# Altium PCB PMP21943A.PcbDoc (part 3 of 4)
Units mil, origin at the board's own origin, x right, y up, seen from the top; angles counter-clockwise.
Board outline 5100 x 3900 mil, 8 copper layers (Top Layer, Signal Layer 1, Signal Layer 2, Signal Layer 3, Signal Layer 4, Signal Layer 5, Signal Layer 6, Bottom Layer), stack 61.6 mil thick; 371 components, 163 nets, 967 pads, 1147 vias.
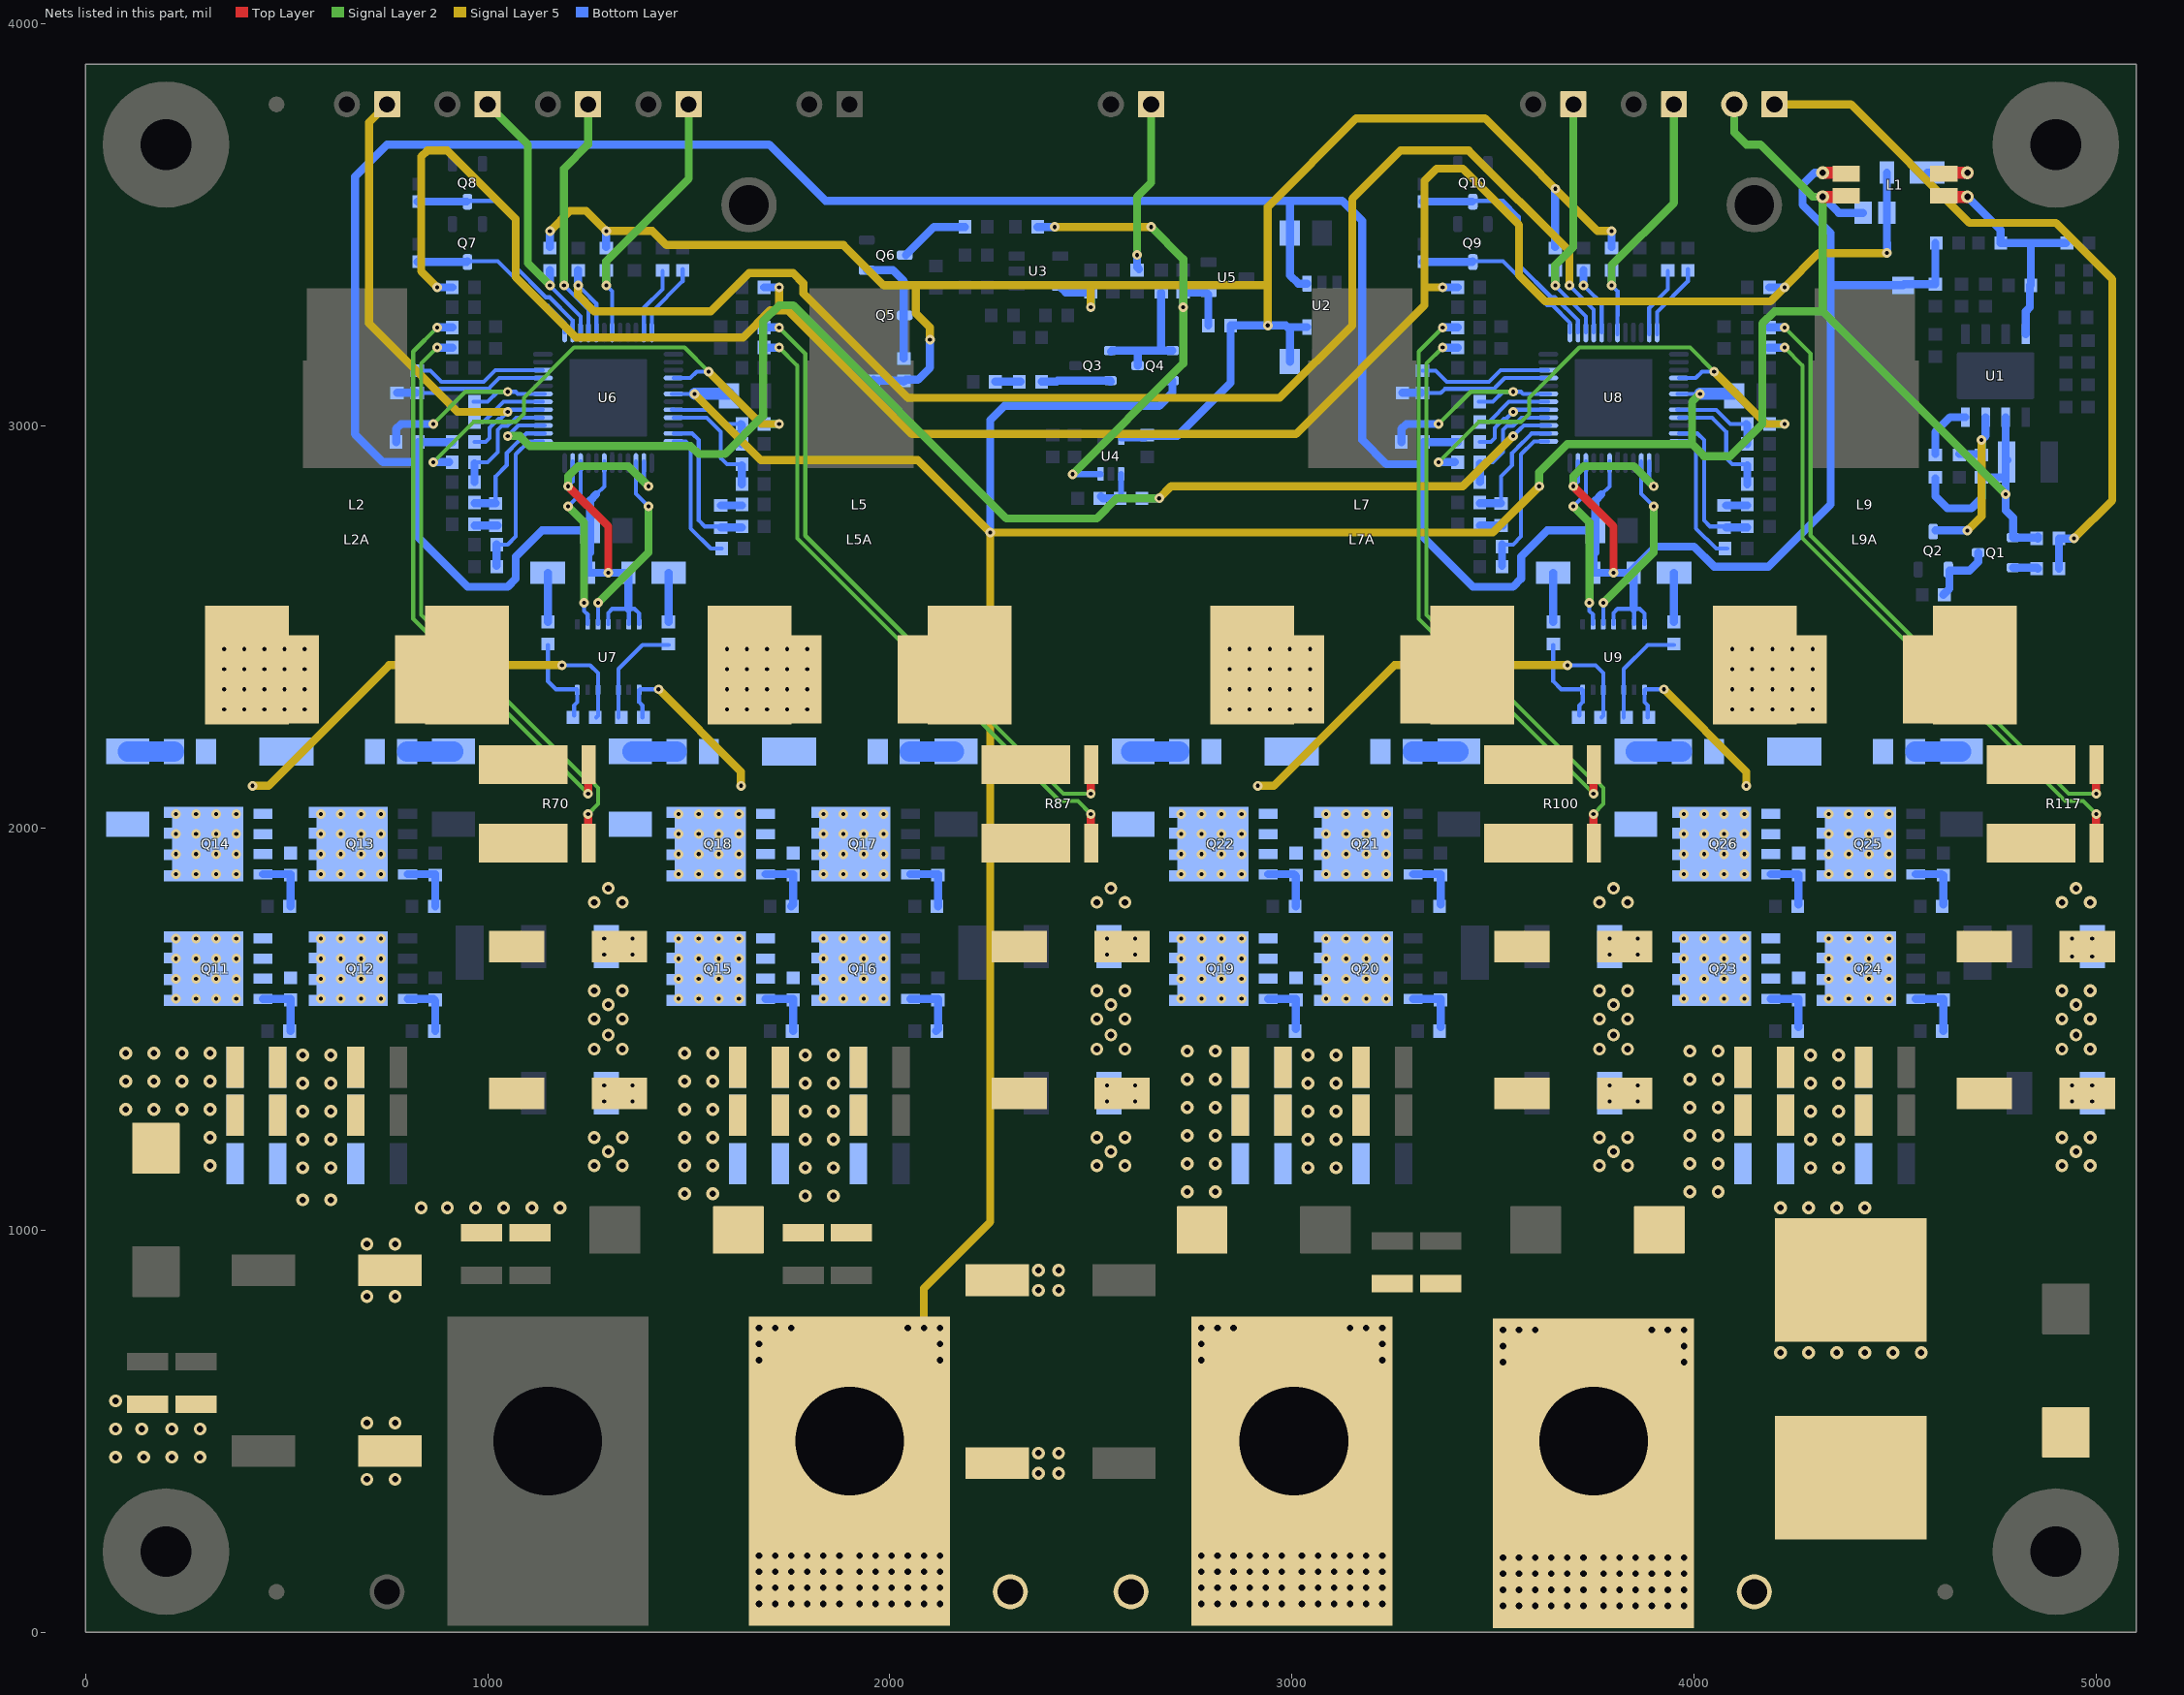
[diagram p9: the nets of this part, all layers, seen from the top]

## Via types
v1: diameter 32, hole 16, Top Layer to Bottom Layer, tented both sides, 555 vias
v2: diameter 24, hole 10, Top Layer to Bottom Layer, tented both sides, 534 vias
v3: diameter 20, hole 10, Top Layer to Bottom Layer, tented both sides, 58 vias

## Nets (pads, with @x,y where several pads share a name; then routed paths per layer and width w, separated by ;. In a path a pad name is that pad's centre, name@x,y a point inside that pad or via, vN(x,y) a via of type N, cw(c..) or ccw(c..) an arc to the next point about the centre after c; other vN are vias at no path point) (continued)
NetC20_1: C20.1 R29.2 U6.28 | length 295.6
  Bottom Layer w10: R29.2@967.56,2910 1000,2910 1025,2935 1025,2990 1035,3000 1049.72,3000 1059.85,3010.13 1060.3,3010.13 1070.96,3020.79 U6.28@1137.6,3020.79
  Bottom Layer w20: C20.1@967.56,2860 R29.2@967.56,2907.44
NetC21_2: C21.2 C22.2 U6.26 | length 305.9
  Bottom Layer w10: C22.2@1020,2805 C22.2@1020,2807.56 1020,2875 1047.56,2902.56 1047.56,2932.56 1075.13,2960.13 1075.3,2960.13 1089.87,2974.7 1089.87,2974.87 1096.42,2981.42 U6.26@1141.54,2981.42
  Bottom Layer w20: C21.2@967.44,2807.56 C22.2@1020,2807.56
NetC22_1: C22.1 R30.1 | length 57.4
  Bottom Layer w20: R30.1@967.56,2752.44 C22.1@1025,2752.44
NetC23_1: C23.1 R31.2 U6.8 | length 237
  Bottom Layer w10: U6.8@1458.46,3040.47 U6.8@1462.4,3040.47 1550,3040 1555,3040 1590,3005 R31.2@1630,3005
  Bottom Layer w20: R31.2@1630,3005 1632.44,3002.56 C23.1@1632.44,2955
NetC28_2: C28.2 R38.1 U7.13 | length 238.9
  Bottom Layer w10: R38.1@1150,2455 1150,2365 1170,2345 1221.54,2345 U7.13@1223.23,2343.31 1223.23,2313.23 1215,2305 C28.2@1215,2280
NetC30_1: C30.1 R42.1 U6.31 | length 537.3
  Signal Layer 2 w10: v2(865,3005) 945,3085 v2(1050,3085)
  Bottom Layer w10: C30.1@965,3060 C30.1@967.56,3060 1000,3060 1025,3085 v2(1050,3085) 1070,3085 1075,3080 ; 1075,3079.84 U6.31@1141.54,3079.84
  Bottom Layer w20: R42.1@772.44,2960 772.44,2992.44 785,3005 v2(865,3005)
NetC32_1: C32.1 R43.1 U7.10 | length 269.9
  Bottom Layer w10: C32.1@1325,2275 1325.59,2275.59 U7.10@1325.59,2343.31 1325.59,2395.59 1385,2455 R43.1@1450,2455
NetC33_1: C33.1 U6.12 | length 350.6
  Bottom Layer w10: U6.12@1462.4,2961.73 1493.27,2961.73 1505,2950 1505,2745 1555,2695 C33.1@1582.44,2695
NetC37_1: C37.1 C40.1 U6.11 | length 383.1
  Bottom Layer w10: U6.11@1462.4,2981.42 1508.58,2981.42 1525,2965 1525,2765 1540,2750 C37.1@1580,2750
  Bottom Layer w20: C37.1@1580,2747.44 C40.1@1632.44,2747.44
NetC37_2: C37.2 R48.2 | length 52.6
  Bottom Layer w20: C37.2@1580,2802.56 R48.2@1632.56,2802.56
NetC38_1: C38.1 R46.2 U6.9 | length 306.7
  Bottom Layer w10: U6.9@1462.4,3020.79 1545,3020.79 1580,2985.79 1580,2920 1595,2905 C38.1@1632.44,2905 C38.1@1635,2905
  Bottom Layer w20: R46.2@1632.44,2855 C38.1@1632.44,2902.56
NetC39_1: C39.1 R47.2 U6.25 | length 393.8
  Bottom Layer w10: R47.2@1022.56,2705 1050,2705 1070,2725 1070,2929.55 1102.19,2961.73 U6.25@1137.6,2961.73
  Bottom Layer w20: C39.1@1022.56,2652.44 R47.2@1022.56,2705
NetC41_1: C41.1 R49.2 U8.28 | length 295.6
  Bottom Layer w10: R49.2@3467.56,2910 3500,2910 3525,2935 3525,2990 3535,3000 3549.72,3000 3559.85,3010.13 3560.3,3010.13 3570.96,3020.79 U8.28@3637.6,3020.79
  Bottom Layer w20: C41.1@3467.56,2860 R49.2@3467.56,2907.44
NetC42_2: C42.2 C43.2 U8.26 | length 305.9
  Bottom Layer w10: C43.2@3520,2805 C43.2@3520,2807.56 3520,2875 3547.56,2902.56 3547.56,2932.56 3575.13,2960.13 3575.3,2960.13 3589.87,2974.7 3589.87,2974.87 3596.42,2981.42 U8.26@3641.54,2981.42
  Bottom Layer w20: C42.2@3467.44,2807.56 C43.2@3520,2807.56
NetC43_1: C43.1 R50.1 | length 57.4
  Bottom Layer w20: R50.1@3467.56,2752.44 C43.1@3525,2752.44
NetC44_1: C44.1 R51.2 U8.8 | length 237
  Bottom Layer w10: U8.8@3958.46,3040.47 U8.8@3962.4,3040.47 4050,3040 4055,3040 4090,3005 R51.2@4130,3005
  Bottom Layer w20: R51.2@4130,3005 4132.44,3002.56 C44.1@4132.44,2955
NetC49_2: C49.2 R58.1 U9.13 | length 238.9
  Bottom Layer w10: R58.1@3650,2455 3650,2365 3670,2345 3721.54,2345 U9.13@3723.23,2343.31 3723.23,2313.23 3715,2305 C49.2@3715,2280
NetC51_1: C51.1 R62.1 U8.31 | length 537.3
  Signal Layer 2 w10: v2(3365,3005) 3445,3085 v2(3550,3085)
  Bottom Layer w10: C51.1@3465,3060 C51.1@3467.56,3060 3500,3060 3525,3085 v2(3550,3085) 3570,3085 3575,3080 ; 3575,3079.84 U8.31@3641.54,3079.84
  Bottom Layer w20: R62.1@3272.44,2960 3272.44,2992.44 3285,3005 v2(3365,3005)
NetC53_1: C53.1 R63.1 U9.10 | length 269.9
  Bottom Layer w10: C53.1@3825,2275 3825.59,2275.59 U9.10@3825.59,2343.31 3825.59,2395.59 3885,2455 R63.1@3950,2455
NetC54_1: C54.1 U8.12 | length 350.6
  Bottom Layer w10: U8.12@3962.4,2961.73 3993.27,2961.73 4005,2950 4005,2745 4055,2695 C54.1@4082.44,2695
NetC58_1: C58.1 C61.1 U8.11 | length 383.1
  Bottom Layer w10: U8.11@3962.4,2981.42 4008.58,2981.42 4025,2965 4025,2765 4040,2750 C58.1@4080,2750
  Bottom Layer w20: C58.1@4080,2747.44 C61.1@4132.44,2747.44
NetC58_2: C58.2 R68.2 | length 52.6
  Bottom Layer w20: C58.2@4080,2802.56 R68.2@4132.56,2802.56
NetC59_1: C59.1 R66.2 U8.9 | length 306.7
  Bottom Layer w10: U8.9@3962.4,3020.79 4045,3020.79 4080,2985.79 4080,2920 4095,2905 R66.2@4132.44,2905 R66.2@4135,2905
  Bottom Layer w20: C59.1@4132.44,2855 R66.2@4132.44,2902.56
NetC60_1: C60.1 R67.2 U8.25 | length 393.8
  Bottom Layer w10: R67.2@3522.56,2705 3550,2705 3570,2725 3570,2929.55 3602.19,2961.73 U8.25@3637.6,2961.73
  Bottom Layer w20: C60.1@3522.56,2652.44 R67.2@3522.56,2705
NetC62_2: C62.2 R69.2 | length 115
  Bottom Layer w50: R69.2@105,2190 C62.2@220,2190
NetC63_2: C63.2 R75.2 | length 115
  Bottom Layer w50: C63.2@800,2190 R75.2@915,2190
NetC67_1: C67.1 C68.1 C69.1 C70.1 C71.1 L3.2 Q11.5 Q11.6 Q11.7 Q11.8 Q11.9 Q14.5 Q14.6 Q14.7 Q14.8 Q14.9 R69.1
  other v1: 310,1160 310,1230 100,1300 170,1300 240,1300 310,1300 100,1370 170,1370 240,1370 310,1370 100,1440 170,1440 240,1440 310,1440
  other v2: 225,1575 275,1575 325,1575 375,1575 225,1625 275,1625 325,1625 375,1625 225,1675 275,1675 325,1675 375,1675 225,1725 275,1725 325,1725 375,1725 225,1885 275,1885 325,1885 375,1885 225,1935 275,1935 325,1935 375,1935 225,1985 275,1985 325,1985 375,1985 225,2035 275,2035 325,2035 375,2035
NetC72_2: C72.2 R82.2
  other v2: 1290,1320 1360,1320 1290,1360 1360,1360
NetC73_2: C73.2 R83.2
  other v2: 1290,1685 1360,1685 1290,1725 1360,1725
NetC74_2: C74.2 J13.1 L4.2 T4.1 TP8.1
  other v1: 3525,65 3565,65 3605,65 3645,65 3685,65 3725,65 3775,65 3815,65 3855,65 3895,65 3935,65 3975,65 3525,105 3565,105 3605,105 3645,105 3685,105 3725,105 3775,105 3815,105 3855,105 3895,105 3935,105 3975,105 3525,145 3565,145 3605,145 3645,145 3685,145 3725,145 3775,145 3815,145 3855,145 3895,145 3935,145 3975,145 3525,185 3565,185 3605,185 3645,185 3685,185 3725,185 3775,185 3815,185 3855,185 3895,185 3935,185 3975,185 3525,671.27 3975,671.27 3525,711.27 3975,711.27 3525,751.27 3565,751.27 3605,751.27 3895,751.27 3935,751.27 3975,751.27
NetC80_2: C80.2 R84.2 | length 110
  Bottom Layer w50: R84.2@1360,2190 C80.2@1470,2190
NetC81_2: C81.2 R85.2
  other v2: 2540,1320 2610,1320 2540,1360 2610,1360
NetC82_2: C82.2 R86.2
  other v2: 2540,1685 2610,1685 2540,1725 2610,1725
NetC88_2: C88.2 R94.2 | length 110
  Bottom Layer w50: C88.2@2050,2190 R94.2@2160,2190
NetC92_1: C92.1 C93.1 C94.1 C95.1 C96.1 L6.2 Q15.5 Q15.6 Q15.7 Q15.8 Q15.9 Q18.5 Q18.6 Q18.7 Q18.8 Q18.9 R84.1
  other v1: 1490,1090 1560,1090 1490,1160 1560,1160 1490,1230 1560,1230 1490,1300 1560,1300 1490,1370 1560,1370 1490,1440 1560,1440
  other v2: 1475,1575 1525,1575 1575,1575 1625,1575 1475,1625 1525,1625 1575,1625 1625,1625 1475,1675 1525,1675 1575,1675 1625,1675 1475,1725 1525,1725 1575,1725 1625,1725 1475,1885 1525,1885 1575,1885 1625,1885 1475,1935 1525,1935 1575,1935 1625,1935 1475,1985 1525,1985 1575,1985 1625,1985 1475,2035 1525,2035 1575,2035 1625,2035
NetC97_2: C97.2 R99.2 | length 120
  Bottom Layer w50: R99.2@2600,2190 C97.2@2720,2190
NetC98_2: C98.2 R105.2 | length 115
  Bottom Layer w50: C98.2@3300,2190 R105.2@3415,2190
NetC102_1: C102.1 C103.1 C104.1 C105.1 C106.1 L8.2 Q19.5 Q19.6 Q19.7 Q19.8 Q19.9 Q22.5 Q22.6 Q22.7 Q22.8 Q22.9 R99.1
  other v1: 2740,1095 2810,1095 2740,1165 2810,1165 2740,1235 2810,1235 2740,1305 2810,1305 2740,1375 2810,1375 2740,1445 2810,1445
  other v2: 2725,1575 2775,1575 2825,1575 2875,1575 2725,1625 2775,1625 2825,1625 2875,1625 2725,1675 2775,1675 2825,1675 2875,1675 2725,1725 2775,1725 2825,1725 2875,1725 2725,1885 2775,1885 2825,1885 2875,1885 2725,1935 2775,1935 2825,1935 2875,1935 2725,1985 2775,1985 2825,1985 2875,1985 2725,2035 2775,2035 2825,2035 2875,2035
NetC107_2: C107.2 R112.2
  other v2: 3790,1320 3860,1320 3790,1360 3860,1360
NetC108_2: C108.2 R113.2
  other v2: 3790,1685 3860,1685 3790,1725 3860,1725
NetC114_2: C114.2 R114.2 | length 115
  Bottom Layer w50: R114.2@3855,2190 C114.2@3970,2190
NetC115_2: C115.2 R115.2
  other v2: 4940,1320 4990,1320 4940,1360 4990,1360
NetC116_2: C116.2 R116.2
  other v2: 4940,1680 4990,1680 4940,1725 4990,1725
NetC122_2: C122.2 R124.2 | length 115
  Bottom Layer w50: C122.2@4550,2190 R124.2@4665,2190
NetC126_1: C126.1 C127.1 C128.1 C129.1 C130.1 L10.2 Q23.5 Q23.6 Q23.7 Q23.8 Q23.9 Q26.5 Q26.6 Q26.7 Q26.8 Q26.9 R114.1
  other v1: 3990,1095 4060,1095 3990,1165 4060,1165 3990,1235 4060,1235 3990,1305 4060,1305 3990,1375 4060,1375 3990,1445 4060,1445
  other v2: 3975,1575 4025,1575 4075,1575 4125,1575 3975,1625 4025,1625 4075,1625 4125,1625 3975,1675 4025,1675 4075,1675 4125,1675 3975,1725 4025,1725 4075,1725 4125,1725 3975,1885 4025,1885 4075,1885 4125,1885 3975,1935 4025,1935 4075,1935 4125,1935 3975,1985 4025,1985 4075,1985 4125,1985 3975,2035 4025,2035 4075,2035 4125,2035
NetD1_1: D1.1 L1.2 | length 150
  Top Layer w30: L1.2@4630,3630 v1(4680,3630)
  Bottom Layer w20: D1.1@4580,3630 v1(4680,3630)
NetD4_2: D4.2 Q7.3 U6.37 | length 455.4
  Bottom Layer w10: Q7.3@950,3410 1025,3410 1135,3300 1148.71,3300 1191.73,3256.98 U6.37@1191.73,3232.4
  Bottom Layer w20: D4.2@825,3408.35 948.35,3408.35 Q7.3@950,3410
NetD5_1: D5.1 R38.2 | length 122.4
  Bottom Layer w20: R38.2@1150,2512.56 D5.1@1150,2635
NetD6_1: D6.1 R43.2 | length 122.4
  Bottom Layer w20: R43.2@1450,2512.56 D6.1@1450,2635
NetD7_2: D7.2 Q8.3 U6.38 | length 608.4
  Bottom Layer w10: Q8.3@950,3560 1025,3560 1065,3520 1065,3400 1145,3320 1153.99,3320 1211.42,3262.57 U6.38@1211.42,3232.4
  Bottom Layer w20: D7.2@825,3558.35 Q8.3@948.35,3558.35
NetD8_2: D8.2 Q9.3 U8.37 | length 455.4
  Bottom Layer w10: Q9.3@3450,3410 3525,3410 3635,3300 3648.71,3300 3691.73,3256.98 U8.37@3691.73,3232.4
  Bottom Layer w20: D8.2@3325,3408.35 3448.35,3408.35 Q9.3@3450,3410
NetD9_1: D9.1 R58.2 | length 122.4
  Bottom Layer w20: R58.2@3650,2512.56 D9.1@3650,2635
NetD10_1: D10.1 R63.2 | length 122.4
  Bottom Layer w20: R63.2@3950,2512.56 D10.1@3950,2635
NetD11_2: D11.2 Q10.3 U8.38 | length 608.4
  Bottom Layer w10: Q10.3@3450,3560 3525,3560 3565,3520 3565,3400 3645,3320 3653.99,3320 3711.42,3262.57 U8.38@3711.42,3232.4
  Bottom Layer w20: D11.2@3325,3558.35 Q10.3@3448.35,3558.35
NetJ1_1: J1.1 R1.2 R2.2 | length 1817
  Signal Layer 5 w20: J1.1@4200,3800 4390,3800 4685,3505 4900,3505 5040,3365 5040,2815 v2(4945,2720)
  Bottom Layer w20: R2.2@4907.56,2645 R1.2@4907.56,2720 v2(4945,2720)
NetJ3_1: J3.1 R14.2 | length 426.6
  Signal Layer 2 w20: v2(2615,3425) 2615,3570 2650,3605 J3.1@2650,3800
  Bottom Layer w20: v2(2615,3425) 2615,3395 R14.2@2620,3390
NetJ4_1: J4.1 U6.40 | length 622.6
  Signal Layer 2 w20: v2(1190,3350) 1190,3640 1250,3700 J4.1@1250,3800 J4.1@1250,3805
  Bottom Layer w10: v2(1190,3350) 1200.13,3339.87 1200.13,3339.7 1250.79,3289.04 U6.40@1250.79,3232.4
NetJ5_1: J5.1 R34.1 U6.39 | length 700.8
  Signal Layer 2 w20: J5.1@1000,3800 1100,3700 1100,3405 v2(1155,3350)
  Bottom Layer w10: v2(1155,3350) 1155,3348.43 1231.1,3272.33 U6.39@1231.1,3232.4
  Bottom Layer w20: v2(1155,3350) R34.1@1155,3387.44
NetJ6_1: J6.1 R40.1 U6.29 | length 1217.9
  Signal Layer 5 w20: J6.1@750,3800 705,3755 705,3255 925,3035 v2(1050,3035)
  Bottom Layer w10: R40.1@967.56,2960 995,2960 1005,2970 1005,2995 1007.13,2997.13 1007.13,2997.4 1027.6,3017.87 1032.87,3017.87 v2(1050,3035) 1055.47,3040.47 U6.29@1137.6,3040.47
NetJ7_1: J7.1 R33.1 U6.43 | length 697.5
  Signal Layer 2 w20: v2@1295,3355 1295,3410 1500,3615 J7.1@1500,3800
  Bottom Layer w10: v2(1295,3350) 1295,3349.82 1310,3334.82 1310,3275 ; v2@1300,3350 v2@1300,3352.35 ; U6.43@1309.84,3228.46 1309.84,3275
  Bottom Layer w20: v2(1295,3350) R33.1@1295,3387.44
NetJ8_1: J8.1 R54.1 U8.39 | length 655.2
  Signal Layer 2 w20: v2(3655,3350) 3655,3400 3700,3445 J8.1@3700,3800
  Bottom Layer w10: v2(3655,3350) 3655,3348.43 3731.1,3272.33 U8.39@3731.1,3232.4
  Bottom Layer w20: v2(3655,3350) R54.1@3655,3387.44
NetJ9_1: J9.1 R53.1 U8.43 | length 681.7
  Signal Layer 2 w20: v2(3795,3350) 3795,3400 3950,3555 J9.1@3950,3800
  Bottom Layer w10: v2(3795,3350) 3795,3349.82 3810,3334.82 3810,3275 ; v2@3800,3350 v2@3800,3352.35 ; U8.43@3809.84,3228.46 3809.84,3275
  Bottom Layer w20: v2(3795,3350) R53.1@3795,3387.44
NetL2_2: L2.2 L2A.2 R70.1
NetL5_2: L5.2 L5A.2 R87.1
NetL7_2: L7.2 L7A.2 R100.1
NetL9_2: L9.2 L9A.2 R117.1
NetQ1_2: Q1.2 R2.1 | length 62.8
  Bottom Layer w20: Q1.2@4793.31,2647.6 4852.4,2647.6 R2.1@4855,2645
NetQ2_3: Q2.3 R3.2 R8.1 U1.3 | length 477.4
  Signal Layer 5 w20: v2(4680,2740) 4715,2775 v2(4715,2965)
  Bottom Layer w20: Q2.3@4600,2740 v2(4680,2740) ; R8.1@4660,2930 4710,2930 4715,2925 R3.2@4715,2927.56 v2(4715,2965) 4725,2975 U1.3@4725,3021.65
NetQ3_1: Q3.1 Q4.1 Q4.3 R15.1 | length 330
  Bottom Layer w20: Q3.1@2550,3185 2552.4,3187.4 Q4.1@2703.31,3187.4 ; Q4.3@2616.69,3150 2616.69,3183.31 ; 2675,3190 R15.1@2675,3332.44
NetQ3_2: Q3.2 R11.2 | length 173.5
  Bottom Layer w20: R11.2@2377.56,3110 2415,3110 2417.6,3112.6 Q3.2@2548.31,3112.6 ; Q3.2@2548.31,3110 Q3.2@2550,3110
NetQ5_3: Q5.3 Q6.1 R13.2 | length 296.1
  Bottom Layer w20: Q6.1@1942.76,3387.6 2007.4,3387.6 2035,3360 R13.2@2035,3167.56
NetQ6_3: Q6.3 R23.1 | length 176.4
  Bottom Layer w20: Q6.3@2040,3425 2110,3495 R23.1@2187.44,3495
NetQ11_4: Q11.4 R71.2 R72.2 | length 148.8
  Bottom Layer w20: Q11.4@441.22,1575 510,1575 R72.2@510,1495
NetQ12_4: Q12.4 R73.1 R78.2 | length 145.9
  Bottom Layer w20: Q12.4@801.22,1575 865,1575 870,1570 R78.2@870,1495
NetQ13_4: Q13.4 R74.1 R79.2 | length 148.8
  Bottom Layer w20: Q13.4@801.22,1885 870,1885 R74.1@870,1882.44 R79.2@870,1805
NetQ14_4: Q14.4 R80.2 R81.2 | length 148.8
  Bottom Layer w20: Q14.4@441.22,1885 510,1885 R80.2@510,1882.44 R81.2@510,1805
NetQ15_4: Q15.4 R88.1 R89.2 | length 148.8
  Bottom Layer w20: Q15.4@1691.22,1575 1760,1575 R89.2@1760,1495
NetQ16_4: Q16.4 R92.1 R95.2 | length 150.9
  Bottom Layer w20: Q16.4@2051.22,1575 2120,1575 2120,1500 R95.2@2115,1495
NetQ17_4: Q17.4 R93.1 R96.2 | length 148.8
  Bottom Layer w20: Q17.4@2051.22,1885 2120,1885 R96.2@2120,1805
NetQ18_4: Q18.4 R97.1 R98.2 | length 150.9
  Bottom Layer w20: Q18.4@1691.22,1885 1760,1885 1760,1810 R98.2@1755,1805
NetQ19_4: Q19.4 R101.2 R102.2 | length 143.8
  Bottom Layer w20: Q19.4@2941.22,1575 3010,1575 R102.2@3010,1500
NetQ20_4: Q20.4 R103.1 R108.2 | length 138.8
  Bottom Layer w20: Q20.4@3301.22,1575 3370,1575 R108.2@3370,1505
NetQ21_4: Q21.4 R104.1 R109.2 | length 143.8
  Bottom Layer w20: Q21.4@3301.22,1885 3370,1885 R109.2@3370,1810
NetQ22_4: Q22.4 R110.2 R111.2 | length 145.9
  Bottom Layer w20: Q22.4@2941.22,1885 3005,1885 3010,1880 R111.2@3010,1805
NetQ23_4: Q23.4 R118.1 R119.2 | length 136.2
  Bottom Layer w20: Q23.4@4191.22,1575 R118.1@4260,1575 ; R119.2@4260,1505 R118.1@4260,1572.44
NetQ24_4: Q24.4 R122.1 R125.2 | length 146.2
  Bottom Layer w20: Q24.4@4551.22,1575 R122.1@4620,1575 ; R125.2@4620,1495 R122.1@4620,1572.44
NetQ25_4: Q25.4 R123.1 R126.2 | length 143.3
  Bottom Layer w20: Q25.4@4551.22,1885 4615,1885 R123.1@4620,1880 ; R126.2@4620,1810 R123.1@4620,1880 ; R123.1@4620,1882.44 R123.1@4620,1880
NetQ26_4: Q26.4 R127.1 R128.2 | length 143.8
  Bottom Layer w20: Q26.4@4191.22,1885 4260,1885 R128.2@4260,1810
NetR4_2: R4.2 U1.4 | length 145.2
  Bottom Layer w20: R4.2@4600,2930 4600,2985 4636.65,3021.65 U1.4@4675,3021.65
NetR11_1: R11.1 R12.2 | length 62.4
  Bottom Layer w20: R12.2@2262.56,3110 R11.1@2322.44,3110 R11.1@2325,3110
NetR18_1: R18.1 R24.2 U4.1 | length 110.5
  Bottom Layer w15: R24.2@2575,2820 2575.59,2820.59 U4.1@2575.59,2880.71
  Bottom Layer w20: R18.1@2525,2825 2530,2820 R24.2@2572.44,2820
NetR29_1: R29.1 R31.1 U6.4 | length 1251.7
  Signal Layer 2 w10: v2(865,2910) 965.13,3010.13 1070,3010.13 1090,3030.13 1090,3070 1215,3195 1490,3195 v2(1550,3135)
  Signal Layer 5 w20: v2(1550,3135) 1680,3005 v2(1725,3005)
  Bottom Layer w10: U6.4@1462.4,3119.21 1504.21,3119.21 1520,3135 v2(1550,3135)
  Bottom Layer w20: v2(865,2910) R29.1@905,2910 ; R31.1@1687.56,3005 v2(1725,3005)
NetR36_1: R36.1 R37.2 U6.33 | length 379.2
  Bottom Layer w9.8: R36.1@825,3082.44 870.21,3082.44 880,3092.23 1002.23,3092.23 1010,3100
  Bottom Layer w10: 1010,3100 1029.21,3119.21 U6.33@1137.6,3119.21 U6.33@1141.54,3119.21
  Bottom Layer w20: R37.2@775,3082.44 R36.1@822.44,3082.44
NetR36_2: R36.2 U6.34 | length 336
  Bottom Layer w10: R36.2@825,3137.56 857.44,3137.56 885,3110 990,3110 1018.9,3138.9 U6.34@1137.6,3138.9
NetR39_2: R39.2 U6.48 | length 193.3
  Bottom Layer w10: U6.48@1408.27,3228.46 U6.48@1408.27,3232.4 1408.27,3283.27 1485,3360 R39.2@1485,3387.44 R39.2@1485,3390
NetR41_2: R41.2 U6.47 | length 175.8
  Bottom Layer w10: U6.47@1388.58,3228.46 1388.58,3293.58 1435,3340 R41.2@1435,3385
NetR44_2: R44.2 U6.30 | length 190.7
  Bottom Layer w10: R44.2@967.56,3010 989.82,3010 1039.82,3060 1065,3060 ; 1065,3060.13 U6.30@1137.6,3060.13
NetR49_1: R49.1 R51.1 U8.4 | length 1251.7
  Signal Layer 2 w10: v2(3365,2910) 3465.13,3010.13 3570,3010.13 3590,3030.13 3590,3070 3715,3195 3990,3195 v2(4050,3135)
  Signal Layer 5 w20: v2(4050,3135) 4180,3005 v2(4225,3005)
  Bottom Layer w10: U8.4@3962.4,3119.21 4004.21,3119.21 4020,3135 v2(4050,3135)
  Bottom Layer w20: v2(3365,2910) R49.1@3405,2910 ; R51.1@4187.56,3005 v2(4225,3005)
NetR55_1: R55.1 U8.41 | length 176.4
  Bottom Layer w10: v2(3725,3350) 3735.13,3339.87 3735.13,3339.7 3770.47,3304.35 U8.41@3770.47,3232.4 ; R55.1@3730,3387.44 R55.1@3730,3390
  Bottom Layer w20: v2(3725,3350) R55.1@3725,3387.44
NetR56_1: R56.1 R57.2 U8.33 | length 379.2
  Bottom Layer w9.8: R56.1@3325,3082.44 3370.21,3082.44 3380,3092.23 3502.23,3092.23 3510,3100
  Bottom Layer w10: 3510,3100 3529.21,3119.21 U8.33@3637.6,3119.21 U8.33@3641.54,3119.21
  Bottom Layer w20: R57.2@3275,3082.44 R56.1@3322.44,3082.44
NetR56_2: R56.2 U8.34 | length 336
  Bottom Layer w10: R56.2@3325,3137.56 3357.44,3137.56 3385,3110 3490,3110 3518.9,3138.9 U8.34@3637.6,3138.9
NetR59_2: R59.2 U8.48 | length 193.3
  Bottom Layer w10: U8.48@3908.27,3228.46 U8.48@3908.27,3232.4 3908.27,3283.27 3985,3360 R59.2@3985,3387.44 R59.2@3985,3390
NetR60_1: R60.1 U8.29 | length 218.2
  Bottom Layer w10: R60.1@3467.56,2960 3495,2960 3505,2970 3505,2995 3507.13,2997.13 3507.13,2997.4 3527.6,3017.87 3532.87,3017.87 v2(3550,3035) 3555.47,3040.47 U8.29@3637.6,3040.47
NetR61_2: R61.2 U8.47 | length 175.8
  Bottom Layer w10: U8.47@3888.58,3228.46 3888.58,3293.58 3935,3340 R61.2@3935,3385
NetR64_2: R64.2 U8.30 | length 190.7
  Bottom Layer w10: R64.2@3467.56,3010 3489.82,3010 3539.82,3060 3565,3060 ; 3565,3060.13 U8.30@3637.6,3060.13
NetR70_3: R70.3 R76.2 | length 1472.5
  Top Layer w20: v2(1250,2085) R70.3@1250,2155
  Signal Layer 2 w10: v2(875,3245) 815,3185 815,2520 v2(1250,2085)
  Bottom Layer w20: v2(875,3245) R76.2@912.44,3245
NetR70_4: R70.4 R77.2 | length 1477.4
  Top Layer w20: R70.4@1250,1970 v2(1250,2035)
  Signal Layer 2 w10: v2(875,3195) 835.07,3155.07 835.07,2529.93 1250,2115 1260,2115 ; v2(1250,2035) 1275,2060 1275,2100.07 1260.03,2115.03
  Bottom Layer w20: v2(875,3195) R77.2@912.44,3195
NetR87_3: R87.3 R90.2 | length 1630.8
  Top Layer w20: v2(2500,2085) R87.3@2500,2155
  Signal Layer 2 w10: v2(1725,3245) 1790,3180 1790,2727.01 2432.01,2085 v2(2500,2085)
  Bottom Layer w20: R90.2@1685,3245 R90.2@1687.56,3245 v2(1725,3245)
NetR87_4: R87.4 R91.2 | length 1617.4
  Top Layer w20: R87.4@2500,1965 v2(2500,2035)
  Signal Layer 2 w10: v2(1725,3195) 1770,3150 1770,2720 2422.87,2067.13 2467.87,2067.13 v2(2500,2035)
  Bottom Layer w20: R91.2@1685,3195 R91.2@1687.56,3195 v2(1725,3195)
NetR100_3: R100.3 R106.2 | length 1472.5
  Top Layer w20: v2(3750,2085) R100.3@3750,2155
  Signal Layer 2 w10: v2(3375,3245) 3315,3185 3315,2520 v2(3750,2085)
  Bottom Layer w20: v2(3375,3245) R106.2@3412.44,3245
NetR100_4: R100.4 R107.2 | length 1487.4
  Top Layer w20: R100.4@3750,1960 v2(3750,2035)
  Signal Layer 2 w10: v2(3375,3195) 3335.07,3155.07 3335.07,2529.93 3750,2115 3760,2115 ; v2(3750,2035) 3775,2060 3775,2100.07 3760.03,2115.03
  Bottom Layer w20: v2(3375,3195) R107.2@3412.44,3195
NetR117_3: R117.3 R120.2 | length 1630.8
  Top Layer w20: v2(5000,2085) R117.3@5000,2155
  Signal Layer 2 w10: v2(4225,3245) 4290,3180 4290,2727.01 4932.01,2085 v2(5000,2085)
  Bottom Layer w20: R120.2@4185,3245 R120.2@4187.56,3245 v2(4225,3245)
NetR117_4: R117.4 R121.2 | length 1617.4
  Top Layer w20: R117.4@5000,1965 v2(5000,2035)
  Signal Layer 2 w10: v2(4225,3195) 4270,3150 4270,2720 4922.87,2067.13 4967.87,2067.13 v2(5000,2035)
  Bottom Layer w20: R121.2@4185,3195 R121.2@4187.56,3195 v2(4225,3195)
NetU6_15: U6.15 U7.3 | length 469.7
  Signal Layer 2 w20: v2(1275,2560) 1400,2685 v2(1400,2800)
  Bottom Layer w10: U7.3@1274.41,2506.69 1274.41,2559.41 v2(1275,2560) ; U6.15@1368.9,2911.54 1368.9,2831.1 v2(1400,2800)
NetU6_22: U6.22 U7.2 | length 437.9
  Signal Layer 2 w20: v2(1200,2800) 1240,2760 v2(1240,2560)
  Bottom Layer w10: v2(1200,2800) 1231.1,2831.1 U6.22@1231.1,2911.54 ; v2(1240,2560) 1240,2540 1248.82,2531.18 U7.2@1248.82,2506.69
NetU8_15: U8.15 U9.3 | length 469.7
  Signal Layer 2 w20: v2(3775,2560) 3900,2685 v2(3900,2800)
  Bottom Layer w10: U9.3@3774.41,2506.69 3774.41,2559.41 v2(3775,2560) ; U8.15@3868.9,2911.54 3868.9,2831.1 v2(3900,2800)
NetU8_22: U8.22 U9.2 | length 437.9
  Signal Layer 2 w20: v2(3700,2800) 3740,2760 v2(3740,2560)
  Bottom Layer w10: v2(3700,2800) 3731.1,2831.1 U8.22@3731.1,2911.54 ; v2(3740,2560) 3740,2540 3748.82,2531.18 U9.2@3748.82,2506.69
NFAULT: R24.1 U6.27 U8.27 | length 3358.7
  Signal Layer 2 w20: v2(1050,2975) 1080,2975 1105,2950 1505,2950 1525,2930 1590,2930 1685,3025 1685,3260 1725,3300 1760,3300 2290,2770 2515,2770 2565,2820 v2(2670,2820)
  Signal Layer 5 w20: v2(2670,2820) 2700,2850 3425,2850 v2(3550,2975)
  Bottom Layer w10: v2(1050,2975) 1067.25,2992.25 1067.71,2992.25 1076.56,3001.1 U6.27@1141.54,3001.1 ; v2(3550,2975) 3567.25,2992.25 3567.71,2992.25 3576.56,3001.1 U8.27@3641.54,3001.1
  Bottom Layer w20: R24.1@2630,2820 v2(2670,2820)
PGND: C1.2 C9.1 C24.1 C45.1 C64.2 C65.2 C66.2 C67.2 C68.2 C69.2 C70.2 C71.2 C72.1 C73.1 C74.1 C75.1 C76.1 C77.1 C78.1 C79.1 C81.1 C82.1 C83.1 C84.1 C85.1 C86.1 C87.1 C89.2 C90.2 C91.2 C92.2 C93.2 C94.2 C95.2 C96.2 C99.2 C100.2 C101.2 C102.2 C103.2 C104.2 C105.2 C106.2 C107.1 C108.1 C109.1 C110.1 C111.1 C112.1 C113.1 C115.1 C116.1 C117.1 C118.1 C119.1 C120.1 C121.1 C123.2 C124.2 C125.2 C126.2 C127.2 C128.2 C129.2 C130.2 J1.2 J10.1 J12.1 L1.4 Q1.1 Q4.2 R1.1 R3.1 R4.1 R70.2 R87.2 R100.2 R117.2 T1.1 T3.1 TP5.1 TP7.1 U1.2 U6.6 U8.6 | length 8754.7
  Top Layer w30: v1(4320,3570) L1.4@4380,3570
  Signal Layer 2 w20: v2(3615,2850) 3615,2885 3685,2955 3995,2955 ; v2(4015,3080) 3995,3060 3995,2955 ; J1.2@4100,3800 4100,3730 4130,3700 4165,3700 4295,3570 v1(4320,3570) 4320,3285 ; v2(4775,2830) 4320,3285 ; 3995,2955 4025,2925 4090,2925 4170,3005 4170,3255 4200,3285 4320,3285
  Signal Layer 5 w20: v2(1515,3080) 1680,2915 2070,2915 v2(2250,2735) ; v1(2085,756.27) 2085,855 2250,1020 v2(2250,2735) ; v2(3615,2850) 3500,2735 v2(2250,2735)
  Bottom Layer w10: U6.6@1458.62,3080 v2(1515,3080) ; U8.6@3958.62,3080 v2(4015,3080)
  Bottom Layer w20: v2(2250,2735) 2250,3015 2285,3050 2670,3050 2703.31,3083.31 Q4.2@2703.31,3112.6 ; v1(4320,3570) 4360,3530 C1.2@4420,3530 ; R4.1@4600,2870 4600,2825 4630,2795 4690,2795 4715,2820 R3.1@4715,2872.44 C9.1@4775,2872.44 ; C9.1@4775,2915 C9.1@4775,2872.44 ; U1.2@4775,3021.65 4775,2920 C9.1@4780,2915 ; R1.1@4855,2720 4855,2725 4852.4,2722.4 Q1.1@4793.31,2722.4 4793.31,2771.69 4775,2790 v2(4775,2830) C9.1@4775,2872.44
  Bottom Layer w30: v2(1515,3080) C24.1@1600,3080 ; v2(4015,3080) C45.1@4100,3080
  other v1: 1675,70 1715,70 1755,70 1795,70 1835,70 1875,70 1925,70 1965,70 2005,70 2045,70 2085,70 2125,70 2775,70 2815,70 2855,70 2895,70 2935,70 2975,70 3025,70 3065,70 3105,70 3145,70 3185,70 3225,70 1675,110 1715,110 1755,110 1795,110 1835,110 1875,110 1925,110 1965,110 2005,110 2045,110 2085,110 2125,110 2775,110 2815,110 2855,110 2895,110 2935,110 2975,110 3025,110 3065,110 3105,110 3145,110 3185,110 3225,110 1675,150 1715,150 1755,150 1795,150 1835,150 1875,150 1925,150 1965,150 2005,150 2045,150 2085,150 2125,150 2775,150 2815,150 2855,150 2895,150 2935,150 2975,150 3025,150 3065,150 3105,150 3145,150 3185,150 3225,150 1675,190 1715,190 1755,190 1795,190 1835,190 1875,190 1925,190 1965,190 2005,190 2045,190 2085,190 2125,190 2775,190 2815,190 2855,190 2895,190 2935,190 2975,190 3025,190 3065,190 3105,190 3145,190 3185,190 3225,190 700,380 770,380 2370,395 2420,395 75,435 145,435 215,435 285,435 2370,445 2420,445 75,505 140,505 215,505 285,505 700,520 770,520 75,575 1675,676.27 2125,676.27 2775,676.27 3225,676.27 4215,695 4285,695 4355,695 4425,695 4495,695 4565,695 1675,716.27 2125,716.27 2775,716.27 3225,716.27 1675,756.27 1715,756.27 1755,756.27 2045,756.27 2125,756.27 2775,756.27 2815,756.27 2855,756.27 3145,756.27 3185,756.27 3225,756.27 700,835 770,835 2370,850 2420,850 2370,900 2420,900 700,965 770,965 835,1055 900,1055 970,1055 1040,1055 1110,1055 1180,1055 4215,1055 4285,1055 4355,1055 4425,1055 540,1075 610,1075 1790,1085 1860,1085 540,1155 610,1155 1790,1155 1860,1155 3040,1155 3110,1155 4290,1155 4360,1155 1265,1160 1335,1160 2515,1160 2585,1160 3765,1160 3835,1160 4915,1160 4985,1160 1300,1195 2550,1195 3800,1195 4950,1195 540,1225 610,1225 1790,1225 1860,1225 3040,1225 3110,1225 4290,1225 4360,1225 1265,1230 1335,1230 2515,1230 2585,1230 3765,1230 3835,1230 4915,1230 4985,1230 540,1295 610,1295 1790,1295 1860,1295 3040,1295 3110,1295 4290,1295 4360,1295 540,1365 610,1365 1790,1365 1860,1365 3040,1365 3110,1365 4290,1365 4360,1365 540,1435 610,1435 1790,1435 1860,1435 3040,1435 3110,1435 4290,1435 4360,1435 1265,1450 1335,1450 2515,1450 2585,1450 3765,1450 3835,1450 4915,1450 4985,1450 1300,1485 2550,1485 3800,1485 4950,1485 1265,1525 1335,1525 2515,1525 2585,1525 3765,1525 3835,1525 4915,1525 4985,1525 1300,1560 2550,1560 3800,1560 4950,1560 1265,1595 1335,1595 2515,1595 2585,1595 3765,1595 3835,1595 4915,1595 4985,1595 1265,1815 1335,1815 2515,1815 2585,1815 3765,1815 3835,1815 4915,1815 4985,1815 1300,1850 2550,1850 3800,1850 4950,1850
REF: C13.1 R19.2 R21.1 U4.3 U5.1 | length 1286.9
  Signal Layer 2 w20: v2(2455,2880) 2730,3155 v2(2730,3295) 2730,3415 v2(2650,3495)
  Signal Layer 5 w20: v2(2410,3495) v2(2650,3495)
  Bottom Layer w15: v2(2455,2880) U4.3@2525,2880
  Bottom Layer w20: R21.1@2367.56,3495 v2(2410,3495) ; v2(2730,3295) C13.1@2730,3332.44 U5.1@2787.44,3332.44 ; R19.2@2792.44,3250 U5.1@2792.44,3327.56
SD: Q1.3 Q2.1 R7.2 | length 170.2
  Bottom Layer w20: R7.2@4620,2580 4635,2595 4635,2640 4685,2640 4706.69,2661.69 Q1.3@4706.69,2685
SW1_1: C28.1 C62.1 C63.1 L2.1 L2A.1 Q11.1 Q11.2 Q11.3 Q12.5 Q12.6 Q12.7 Q12.8 Q12.9 Q13.5 Q13.6 Q13.7 Q13.8 Q13.9 Q14.1 Q14.2 Q14.3 R71.1 R80.1 TP3.1 U7.11 | length 1104.1
  Signal Layer 5 w20: v2(415,2105) 455,2105 755,2405 v2(1185,2405)
  Bottom Layer w10: v2(1185,2405) 1255,2405 1274.41,2385.59 U7.11@1274.41,2343.31 1274.41,2279.41 C28.1@1270,2275
  other v2: 585,1575 635,1575 685,1575 735,1575 585,1625 635,1625 685,1625 735,1625 585,1675 635,1675 685,1675 735,1675 585,1725 635,1725 685,1725 735,1725 585,1885 635,1885 685,1885 735,1885 585,1935 635,1935 685,1935 735,1935 585,1985 635,1985 685,1985 735,1985 585,2035 635,2035 685,2035 735,2035 345,2295 395,2295 445,2295 495,2295 545,2295 345,2345 395,2345 445,2345 495,2345 545,2345 345,2395 395,2395 445,2395 495,2395 545,2395 345,2445 395,2445 445,2445 495,2445 545,2445
SW1_2: C49.1 C97.1 C98.1 L7.1 L7A.1 Q19.1 Q19.2 Q19.3 Q20.5 Q20.6 Q20.7 Q20.8 Q20.9 Q21.5 Q21.6 Q21.7 Q21.8 Q21.9 Q22.1 Q22.2 Q22.3 R101.1 R110.1 TP11.1 U9.11 | length 1104.1
  Signal Layer 5 w20: v2(2915,2105) 2955,2105 3255,2405 v2(3685,2405)
  Bottom Layer w10: v2(3685,2405) 3755,2405 3774.41,2385.59 U9.11@3774.41,2343.31 3774.41,2279.41 C49.1@3770,2275
  other v2: 3085,1575 3135,1575 3185,1575 3235,1575 3085,1625 3135,1625 3185,1625 3235,1625 3085,1675 3135,1675 3185,1675 3235,1675 3085,1725 3135,1725 3185,1725 3235,1725 3085,1885 3135,1885 3185,1885 3235,1885 3085,1935 3135,1935 3185,1935 3235,1935 3085,1985 3135,1985 3185,1985 3235,1985 3085,2035 3135,2035 3185,2035 3235,2035 2845,2295 2895,2295 2945,2295 2995,2295 3045,2295 2845,2345 2895,2345 2945,2345 2995,2345 3045,2345 2845,2395 2895,2395 2945,2395 2995,2395 3045,2395 2845,2445 2895,2445 2945,2445 2995,2445 3045,2445
SW2_1: C32.2 C80.1 C88.1 L5.1 L5A.1 Q15.1 Q15.2 Q15.3 Q16.5 Q16.6 Q16.7 Q16.8 Q16.9 Q17.5 Q17.6 Q17.7 Q17.8 Q17.9 Q18.1 Q18.2 Q18.3 R88.2 R97.2 TP9.1 U7.8 | length 441.6
  Signal Layer 5 w20: v2(1425,2345) 1630,2140 v2(1630,2105)
  Bottom Layer w10: U7.8@1376.77,2343.31 1376.77,2313.23 1385,2305 C32.2@1385,2275 ; U7.8@1380,2345 v2(1425,2345)
  other v2: 1835,1575 1885,1575 1935,1575 1985,1575 1835,1625 1885,1625 1935,1625 1985,1625 1835,1675 1885,1675 1935,1675 1985,1675 1835,1725 1885,1725 1935,1725 1985,1725 1835,1885 1885,1885 1935,1885 1985,1885 1835,1935 1885,1935 1935,1935 1985,1935 1835,1985 1885,1985 1935,1985 1985,1985 1835,2035 1885,2035 1935,2035 1985,2035 1595,2295 1645,2295 1695,2295 1745,2295 1795,2295 1595,2345 1645,2345 1695,2345 1745,2345 1795,2345 1595,2395 1645,2395 1695,2395 1745,2395 1795,2395 1595,2445 1645,2445 1695,2445 1745,2445 1795,2445
SW2_2: C53.2 C114.1 C122.1 L9.1 L9A.1 Q23.1 Q23.2 Q23.3 Q24.5 Q24.6 Q24.7 Q24.8 Q24.9 Q25.5 Q25.6 Q25.7 Q25.8 Q25.9 Q26.1 Q26.2 Q26.3 R118.2 R127.2 TP13.1 U9.8 | length 441.6
  Signal Layer 5 w20: v2(3925,2345) 4130,2140 v2(4130,2105)
  Bottom Layer w10: U9.8@3876.77,2343.31 3876.77,2313.23 3885,2305 C53.2@3885,2275 ; U9.8@3880,2345 v2(3925,2345)
  other v2: 4335,1575 4385,1575 4435,1575 4485,1575 4335,1625 4385,1625 4435,1625 4485,1625 4335,1675 4385,1675 4435,1675 4485,1675 4335,1725 4385,1725 4435,1725 4485,1725 4335,1885 4385,1885 4435,1885 4485,1885 4335,1935 4385,1935 4435,1935 4485,1935 4335,1985 4385,1985 4435,1985 4485,1985 4335,2035 4385,2035 4435,2035 4485,2035 4095,2295 4145,2295 4195,2295 4245,2295 4295,2295 4095,2345 4145,2345 4195,2345 4245,2345 4295,2345 4095,2395 4145,2395 4195,2395 4245,2395 4295,2395 4095,2445 4145,2445 4195,2445 4245,2445 4295,2445
SWBIAS: C2.2 C17.1 L1.1 R5.2 U1.8 | length 606
  Top Layer w30: L1.1@4620,3570 v1(4680,3570)
  Bottom Layer w20: v1(4680,3570) 4762.56,3487.44 R5.2@4762.56,3455 4840,3455 ; U1.8@4825,3228.35 4825,3285 4835,3295 4835,3350 C2.2@4837.56,3350 4837.56,3452.56 4840,3455 ; C17.1@4925,3455 4840,3455
SYNC: R35.1 U6.41 U8.40 | length 3636
  Signal Layer 5 w20: v2(1225,3350) 1225,3325 1265,3285 1555,3285 1650,3380 1760,3380 1785,3355 1785,3330 2045,3070 2970,3070 3150,3250 3150,3565 3270,3685 3440,3685 3690,3435 v2(3690,3350)
  Bottom Layer w10: v2(1225,3350) 1235.13,3339.87 1235.13,3339.7 1270.47,3304.35 U6.41@1270.47,3232.4 ; R35.1@1230,3387.44 R35.1@1230,3390 ; v2(3690,3350) 3700.13,3339.87 3700.13,3339.7 3750.79,3289.04 U8.40@3750.79,3232.4
  Bottom Layer w20: v2(1225,3350) R35.1@1225,3387.44
V5: C6.1 C12.1 C16.2 R10.2 R13.1 R19.1 R33.2 R34.2 R53.2 R54.2 U2.5 U3.5 U4.5 | length 4803.9
  Signal Layer 5 w20: v2(1155,3485) 1205,3535 1245,3535 v2(1295,3485) 1410,3485 1445,3450 1885,3450 1985,3350 2065,3350 ; v2(2100,3215) 2100,3245 2065,3280 2065,3350 ; v2(2500,3295) 2500,3350 ; v2(2940,3250) 2940,3350 ; v2(3795,3485) 3760,3485 3480,3765 3160,3765 2940,3545 2940,3350 ; 2065,3350 2500,3350 ; 2500,3350 2940,3350
  Bottom Layer w15: U4.5@2575.59,2969.29 2634.29,2969.29 C16.2@2640,2975
  Bottom Layer w20: R34.2@1155,3445 v2(1155,3485) ; R33.2@1295,3445 v2(1295,3485) ; R10.2@1960,3115 1962.56,3112.44 R13.1@2035,3112.44 ; R13.1@2035,3110 2040,3115 2070,3115 2100,3145 v2(2100,3215) ; U3.5@2425,3345 2437.56,3332.44 C12.1@2500,3332.44 v2(2500,3295) ; C16.2@2640,2975 2715,2975 2847.56,3107.56 R19.1@2847.56,3250 v2(2940,3250) 2985,3250 2989.13,3245.87 ; C6.1@2995,3160 2995,3240 2989.13,3245.87 ; U2.5@3037.6,3245.87 2989.13,3245.87 ; R54.2@3655,3445 v2(3655,3590) ; R53.2@3795,3445 v2(3795,3485)
V10: C3.1 C4.2 C8.1 C29.1 C50.1 D5.2 D6.2 D9.2 D10.2 L1.3 R6.2 R40.2 R42.2 R60.2 R62.2 U2.1 U6.14 U6.19 U6.23 U7.4 U7.6 U7.7 U8.14 U8.19 U8.23 U9.4 U9.6 U9.7 | length 10700.9
  Top Layer w20: v2(1200,2850) 1300,2750 v2@1300,2640 ; v2(3700,2850) 3800,2750 v2@3800,2640
  Top Layer w30: v1(4320,3630) L1.3@4380,3630
  Signal Layer 2 w20: v2(1200,2850) 1200,2875 1225,2900 1350,2900 v2(1400,2850) ; v2(3700,2850) 3700,2875 3725,2900 3850,2900 v2(3900,2850)
  Bottom Layer w10: v2(1200,2850) 1211.42,2861.42 U6.23@1211.42,2911.54 ; 1270,2830 1290.16,2849.32 U6.19@1290.16,2911.54 ; U7.4@1300,2506.69 1300,2535 1310,2545 1351.18,2545 ; U7.6@1351.18,2506.69 1351.18,2545 ; U7.7@1376.77,2506.69 1376.77,2533.23 1365,2545 1351.18,2545 ; U6.14@1388.58,2911.54 1388.58,2861.42 v2(1400,2850) ; v2(3700,2850) 3711.42,2861.42 U8.23@3711.42,2911.54 ; 3770,2830 3790.16,2849.32 U8.19@3790.16,2911.54 ; U9.4@3800,2506.69 3800,2535 3810,2545 3851.18,2545 ; U9.6@3851.18,2506.69 3851.18,2545 ; U9.7@3876.77,2506.69 3876.77,2533.23 3865,2545 3851.18,2545 ; U8.14@3888.58,2911.54 3888.58,2861.42 v2(3900,2850)
  Bottom Layer w20: R42.2@827.56,2960 827.56,2910 ; R42.2@830,2960 R40.2@912.44,2960 ; D5.2@1250.2,2635 D5.2@1250.2,2639.8 ; 1270,2830 1255,2815 C29.1@1255,2740 ; 1349.8,2545.2 D6.2@1349.8,2635 v2(1300,2635) 1255,2635 D5.2@1250.2,2639.8 ; U2.1@3037.6,3354.13 3015.87,3354.13 2995,3375 C3.1@2995,3480 2995,3560 ; R60.2@3412.44,2960 R62.2@3327.56,2960 3327.56,2905 ; D9.2@3750.2,2635 D9.2@3750.2,2639.8 ; 3770,2830 3755,2815 C50.1@3755,2740 ; D10.2@3845,2640 3905,2700 4000,2700 4050,2650 4185,2650 4340,2805 4340,3350 ; 3849.8,2545.2 D10.2@3849.8,2635 v2(3800,2635) 3755,2635 D9.2@3750.2,2639.8 ; v1(4320,3630) 4300,3630 4270,3600 4270,3550 4340,3480 4340,3350 ; R6.2@4600,3352.56 4522.56,3352.56 4520,3350 4340,3350 ; R6.2@4600,3355 C4.2@4600,3455 ; 827.56,2910 740,2910 670,2980 670,3620 750,3700 1700,3700 1840,3560 2995,3560 ; 827.56,2910 827.56,2722.44 950,2600 1050,2600 1070,2620 1070,2675 1135,2740 C29.1@1255,2740 ; D5.2@1250.2,2639.8 1250.2,2680.2 1255,2685 C29.1@1255,2740 ; 2995,3560 3125,3560 3175,3510 3175,2965 3235,2905 3327.56,2905 ; 3327.56,2905 3327.56,2722.44 3450,2600 3550,2600 3570,2620 3570,2675 3635,2740 C50.1@3755,2740 ; D9.2@3750.2,2639.8 3750.2,2680.2 3755,2685 C50.1@3755,2740
Vneg10: C1.1 D1.2 R32.2 R45.1 R52.2 R65.1 | length 5595
  Signal Layer 5 w20: v2(875,3345) 835,3385 835,3670 850,3685 900,3685 1070,3515 1070,3370 1220,3220 1635,3220 1702.5,3287.5 1747.5,3287.5 2055,2980 3010,2980 3330,3300 3330,3345 ; v2(1725,3345) 1725,3290 1730,3290 ; v2(3375,3345) 3330,3345 ; v2(4480,3430) 4310,3430 v2(4225,3345) 4190,3310 3630,3310 3565,3375 3565,3500 3425,3640 3360,3640 3330,3610 3330,3345
  Bottom Layer w20: v2(875,3345) R32.2@912.44,3345 ; R45.1@1687.56,3345 v2(1725,3345) ; v2(3375,3345) R52.2@3412.44,3345 ; R65.1@4187.56,3345 v2(4225,3345) ; C1.1@4479.53,3530 4479.53,3455.47 4480,3455 v2(4480,3430) ; C1.1@4479.8,3530.2 D1.2@4479.8,3630
pads on no net: FID1.1 FID2.1 FID3.1 H1.1 H2.1 H3.1 H4.1 H5.0 H6.0 H7.0 H8.0 L2.3 L2A.3 L5.3 L5A.3 L7.3 L7A.3 L9.3 L9A.3 LBL1.0 U1.9@4750,3125 U2.3 U2.4 U5.3 U6.3 U6.5 U6.7 U6.16 U6.21 U6.32 U8.3 U8.5 U8.7 U8.16 U8.21 U8.32

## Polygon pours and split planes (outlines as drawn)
+VOUT on Bottom Layer "+VOUT_L08_P1034" (solid, remove dead copper, pour order 1034): 0,0 0,1100 5100,1100 5100,0
AGND on Bottom Layer "AGND_L08_P1032" (solid, remove dead copper, pour order 1032): 4320,3900 4320,2625 0,2625 0,3900
-VIN on Bottom Layer "-VIN_L08_P1036" (solid, remove dead copper, pour order 1036): 5100,2600 5100,3900 4350,3900 4350,2600 0,2600 0,1135 5100,1135
-VIN on Signal Layer 1 "-VIN_L02_P932" (solid, remove dead copper, pour order 932): 3580,2600 3580,2835 3665,2920 3945,2920 4020,2845 4020,2600 5100,2600 5100,0 0,0 0,2600 1080,2600 1080,2850 1150,2920 1450,2920 1520,2850 1520,2600
AGND on Signal Layer 1 "AGND_L02_P930" (solid, remove dead copper, pour order 930): 0,2630 0,3900 5100,3900 5100,2630
+VOUT on Signal Layer 2 "+VOUT_L03_P951" (solid, remove dead copper, pour order 951): 0,0 0,1100 5100,1100 5100,0
AGND on Signal Layer 2 "AGND_L03_P949" (solid, remove dead copper, pour order 949): 0,2950 0,3900 5100,3900 5100,2950
-VIN on Signal Layer 2 "-VIN_L03_P952" (solid, remove dead copper, pour order 952): 0,1135 0,2925 5100,2925 5100,1135
AGND on Top Layer "AGND_L01_P910" (solid, remove dead copper, pour order 910): 0,2950 0,3900 5100,3900 5100,2950
-VIN on Top Layer "-VIN_L01_P913" (solid, remove dead copper, pour order 913): 5100,2925 5100,0 0,0 0,2925
-VIN on Signal Layer 3 "-VIN_L04_P967" (solid, remove dead copper, pour order 967): 5100,1910 5100,2925 0,2925 0,1910
AGND on Signal Layer 3 "AGND_L04_P965" (solid, remove dead copper, pour order 965): 5100,2950 5100,3900 0,3900 0,2950
PGND on Signal Layer 3 "PGND_L04_P968" (solid, remove dead copper, pour order 968): 5100,1875 5100,0 0,0 0,1875
-VIN on Signal Layer 6 "-VIN_L07_P1021" (solid, remove dead copper, pour order 1021): 3580,2600 3580,2835 3665,2920 3945,2920 4020,2845 4020,2600 5100,2600 5100,0 0,0 0,2600 1080,2600 1080,2850 1150,2920 1450,2920 1520,2850 1520,2600
AGND on Signal Layer 6 "AGND_L07_P1022" (solid, remove dead copper, pour order 1022): 5100,3900 5100,2630 0,2630 0,3900
PGND on Signal Layer 5 "PGND_L06_P987" (solid, remove dead copper, pour order 987): 0,0 0,1465 5100,1465 5100,0
AGND on Signal Layer 5 "AGND_L06_P985" (solid, remove dead copper, pour order 985): 0,2950 0,3900 5100,3900 5100,2950
-VIN on Signal Layer 5 "-VIN_L06_P988" (solid, remove dead copper, pour order 988): 5100,1500 0,1500 0,2925 5100,2925
AGND on Signal Layer 4 "AGND_L05_P1001" (solid, remove dead copper, pour order 1001): 0,2950 0,3900 5100,3900 5100,2950
+VOUT on Signal Layer 4 "+VOUT_L05_P1004" (solid, remove dead copper, pour order 1004): 5100,0 0,0 0,2915 5100,2915

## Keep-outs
Keep-Out Layer:
  lines w10: -5,-5 -5,3905 5105,3905 5105,-5 -5,-5
  text ".Layer_Name" at 77,-858.49 h60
